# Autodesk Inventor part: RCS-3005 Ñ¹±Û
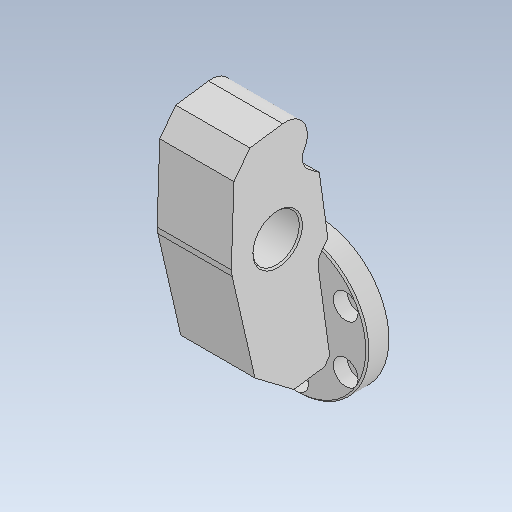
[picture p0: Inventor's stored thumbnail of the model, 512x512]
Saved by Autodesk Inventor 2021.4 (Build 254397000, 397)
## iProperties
Created: 2019-12
Part Number: RCS-3005 Ñ¹±Û
Material: Ogólny
Document SubType Name: Modeling
Designer: user
Density: 1 g/cm^3
Appearance: Domyślna
Author: user
Revision Number: ÈÎºÎ
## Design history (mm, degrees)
feature "Body.5"
feature "Body.4"
node "Bryła1"
node "Bryła2"
